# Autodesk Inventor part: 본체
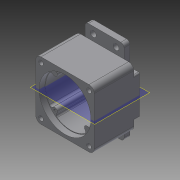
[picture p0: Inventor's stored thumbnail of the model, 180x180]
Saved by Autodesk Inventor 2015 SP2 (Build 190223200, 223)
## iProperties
Created: 2015-06
Part Number: 본체
Material: 일반
Document SubType Name: Modeling
Designer: AMC
Density: 1 g/cm^3
Appearance: 기본값
Author: AMC
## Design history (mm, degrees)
sketch "스케치1"
  geometry: L1 (-45, 45)-(45, 45); L2 (45, 45)-(45, -45); L3 (45, -45)-(-45, -45); L4 (-45, -45)-(-45, 45); 3 further points
  constraints: 8 end point, 2 midpoint, 2 parallel, 1 horizontal, 1 horizontal alignment, 1 perpendicular, 1 vertical alignment
  dimensions: "d0" = 90 distance of L2.end L3.end; "d1" = 90 distance of L1.end L2.end
extrude "돌출1" new body sketch "스케치1" distance "d2" = 61; taper "d3" = 0 deg
sketch "스케치2"
  geometry: C1 r 40 at (0, 0); 1 further point
  constraints: 1 centre point, 1 coincident
  dimensions: "d4" = 80 diameter of C1
extrude "돌출2" cut sketch "스케치2" distance "d5" = 9; taper "d6" = 0 deg
sketch "스케치3"
  geometry: C1 r 39 at (0, 0); 1 further point
  constraints: 1 centre point, 1 coincident
  dimensions: "d7" = 78 diameter of C1
extrude "돌출3" cut sketch "스케치3" distance "d8" = 61; taper "d9" = 0 deg
sketch "스케치5"
  geometry: L1 (-30, -65)-(30, -65); L2 (30, -65)-(30, 65); L3 (30, 65)-(-30, 65); L4 (-30, 65)-(-30, -65); L5 (-45, 45)-(-45, -45) reference; L6 (45, 45)-(45, -45) reference; L7 (-45, -30)-(45, -30); L8 (45, -30)-(45, 30); L9 (45, 30)-(-45, 30); L10 (-45, 30)-(-45, -30); 5 further points
  constraints: 16 end point, 4 midpoint, 4 parallel, 2 horizontal, 2 horizontal alignment, 2 perpendicular, 2 point on line, 1 vertical alignment
  dimensions: "d24" = 130 distance between parallel lines of L3 L1; "d25" = 60 distance of L1.start L1.end; "d28" = 60 distance between parallel lines of L9 L7
extrude "돌출4" join sketch "스케치5" distance "d26" = 9; taper "d27" = 0 deg
sketch "스케치7"
  geometry: C1 r 25 at (-11, 0); 1 further point
  constraints: 1 centre point
  dimensions: "d31" = 50 diameter of C1; "d32" = 11 distance of point (0, 0) C1.centre
extrude "돌출5" join sketch "스케치7" distance "d33" = 7; taper "d34" = 0 deg
sketch "스케치13"
  geometry: L1 (45, 45)-(45, -45) reference; L2 (45, -45)-(-45, -45) reference; L3 (-45, -45)-(-45, 45) reference; L4 (-45, 45)-(45, 45) reference; L5 (0, 0)-(-24.749, 24.749); L6 (0, 0)-(-33.462, 0); L7 (-21.763, 27.411)-(-24.429, 30.401); L8 (-27.411, 21.763)-(-30.401, 24.429); C1 r 40 at (0, 0) reference; C2 r 39 at (0, 0) reference; A1 r 39 centre (0, 0) between (-24.429, 30.401) and (-30.401, 24.429) reference; A2 r 4 centre (-24.749, 24.749) between (-27.411, 21.763) and (-21.763, 27.411); A3 r 35 centre (0, 0) between (-21.763, 27.411) and (-27.411, 21.763); 1 further point
  constraints: 8 end point, 6 point on circle, 2 centre point, 2 coincident, 2 tangent, 1 horizontal
  dimensions: "d56" = 35 distance of L5.start L5.end; "d57" = 45 deg angle of L6 L5; "d58" = 8 diameter of A2; "d59" = 70 diameter of A3
extrude "돌출8" join sketch "스케치13" stored distance "d60" = 20; taper "d61" = 0 deg
fillet "모깎기2" dims "d62" = 3.5
sketch "스케치17"
  geometry: A1 r 20.5 centre (11, 0) between (-8.117, -7.402) and (-8.117, 7.402); A2 r 14 centre (-20, 0) between (-8.117, 7.402) and (-8.117, -7.402); 1 further point
  constraints: 4 point on circle, 2 centre point, 2 horizontal alignment
  dimensions: "d73" = 41 diameter of A1; "d74" = 28 diameter of A2; "d75" = 11 distance of point (0, 0) A1.centre; "d76" = 20 distance of point (0, 0) A2.centre
extrude "돌출10" join sketch "스케치17" distance "d77" = 7; taper "d78" = 0 deg
sketch "스케치18"
  geometry: L1 (-40, 61)-(-40, 52) reference; L2 (-40, 52)-(-39, 52) reference; L3 (-39, 52)-(-39, 0) reference; L4 (-39, 0)-(-31.5, 0) reference; L5 (-31.5, 0)-(-31.5, 7) reference; L6 (-31.5, 7)-(34, 7) reference; L7 (34, 7)-(34, 0) reference; L8 (34, 0)-(39, 0) reference; L9 (39, 0)-(39, 52) reference; L10 (39, 52)-(40, 52) reference; L11 (40, 52)-(40, 61) reference; L12 (40, 61)-(45, 61) reference; L13 (45, 61)-(45, -9) reference; L14 (45, -9)-(14, -9) reference; L15 (14, -9)-(14, -16) reference; L16 (14, -16)-(-36, -16) reference; L17 (-36, -16)-(-36, -9) reference; L18 (-36, -9)-(-45, -9) reference; L19 (-45, -9)-(-45, 61) reference; L20 (-45, 61)-(-40, 61) reference; L21 (-36, -16)-(14, -16) reference; L22 (-11, -16)-(-11, 7); L23 (-11, -16)-(-27, -16); L24 (-27, -16)-(-27, -8); L25 (-27, -8)-(-23.5, -8); L26 (-23.5, -8)-(-23.5, -3); L27 (-28.5, 7)-(-11, 7); L28 (8.117, 7)-(-31.5, 7) reference; L29 (-23.5, -3)-(-28.5, -3); L30 (-28.5, -3)-(-28.5, 7); 1 further point
  constraints: 16 end point, 4 perpendicular, 3 point on line, 1 collinear, 1 horizontal, 1 midpoint, 1 vertical
  dimensions: "d79" = 11 distance from line of point (0, 0) L22; "d80" = 32 diameter of L24 L22; "d81" = 8 distance of L23.end L24.end; "d82" = 10 distance of L29.end L27.start; "d83" = 25 diameter of L26 L22; "d84" = 35 diameter of L30 L22
revolve "회전2" sketch "스케치18" stored, may be unused: angle "d85" = 90 deg
sketch "스케치19"
  geometry: L1 (40, 52)-(40, 61) reference; L2 (40, 61)-(45, 61) reference; L3 (45, 61)-(45, -9) reference; L4 (45, -9)-(14, -9) reference; L5 (14, -9)-(14, -16) reference; L6 (14, -16)-(5, -16) reference; L7 (5, -16)-(5, -8) reference; L8 (5, -8)-(1.5, -8) reference; L9 (1.5, -8)-(1.5, -3) reference; L10 (1.5, -3)-(6.5, -3) reference; L11 (6.5, -3)-(6.5, 7) reference; L12 (6.5, 7)-(34, 7) reference; L13 (34, 7)-(34, 0) reference; L14 (34, 0)-(39, 0) reference; L15 (39, 0)-(39, 52) reference; L16 (39, 52)-(40, 52) reference; L17 (-40, 61)-(-40, 52) reference; L18 (-40, 52)-(-39, 52) reference; L19 (-39, 52)-(-39, 0) reference; L20 (-39, 0)-(-31.5, 0) reference; L21 (-31.5, 0)-(-31.5, 7) reference; L22 (-31.5, 7)-(-28.5, 7) reference; L23 (-28.5, 7)-(-28.5, -3) reference; L24 (-28.5, -3)-(-23.5, -3) reference; L25 (-23.5, -3)-(-23.5, -8) reference; L26 (-23.5, -8)-(-27, -8) reference; L27 (-27, -8)-(-27, -16) reference; L28 (-27, -16)-(-36, -16) reference; L29 (-36, -16)-(-36, -9) reference; L30 (-36, -9)-(-45, -9) reference; L31 (-45, -9)-(-45, 61) reference; L32 (-45, 61)-(-40, 61) reference; L33 (-30, -9)-(30, -9) reference; L34 (20, 0)-(20, 7); L35 (20, 0)-(9, 0); L36 (9, 0)-(9, 7); L37 (10.5, 0)-(10.5, 0); 1 further point
  constraints: 8 end point, 4 perpendicular, 3 point on line
  dimensions: "d86" = 20 horizontal distance of point (0, 0) L34.end; "d87" = 22 diameter of L36 L34; "d88" = 7 distance of L35.end L36.end; "d89" = 19 diameter of L37 L34
revolve "회전3" sketch "스케치19" stored, may be unused: angle "d92" = 90 deg
sketch "스케치20"
  geometry: L1 (40, 52)-(40, 61) reference; L2 (40, 61)-(45, 61) reference; L3 (45, 61)-(45, -9) reference; L4 (45, -9)-(14, -9) reference; L5 (14, -9)-(14, -16) reference; L6 (14, -16)-(5, -16) reference; L7 (5, -16)-(5, -8) reference; L8 (5, -8)-(1.5, -8) reference; L9 (1.5, -8)-(1.5, -3) reference; L10 (1.5, -3)-(6.5, -3) reference; L11 (6.5, -3)-(6.5, 7) reference; L12 (6.5, 7)-(9, 7) reference; L13 (9, 7)-(9, 0) reference; L14 (9, 0)-(31, 0) reference; L15 (31, 0)-(31, 7) reference; L16 (31, 7)-(34, 7) reference; L17 (34, 7)-(34, 0) reference; L18 (34, 0)-(39, 0) reference; L19 (39, 0)-(39, 52) reference; L20 (39, 52)-(40, 52) reference; L21 (-40, 61)-(-40, 52) reference; L22 (-40, 52)-(-39, 52) reference; L23 (-39, 52)-(-39, 0) reference; L24 (-39, 0)-(-31.5, 0) reference; L25 (-31.5, 0)-(-31.5, 7) reference; L26 (-31.5, 7)-(-28.5, 7) reference; L27 (-28.5, 7)-(-28.5, -3) reference; L28 (-28.5, -3)-(-23.5, -3) reference; L29 (-23.5, -3)-(-23.5, -8) reference; L30 (-23.5, -8)-(-27, -8) reference; L31 (-27, -8)-(-27, -16) reference; L32 (-27, -16)-(-36, -16) reference; L33 (-36, -16)-(-36, -9) reference; L34 (-36, -9)-(-45, -9) reference; L35 (-45, -9)-(-45, 61) reference; L36 (-45, 61)-(-40, 61) reference; L37 (9, 0)-(31, 0) reference; L38 (20, 0)-(20, -1); L39 (20, -1)-(10.5, -1); L40 (10.5, -1)-(10.5, 0); 1 further point
  constraints: 6 end point, 1 horizontal, 1 midpoint, 1 perpendicular, 1 point on line, 1 vertical
  dimensions: "d93" = 19 diameter of L40 L38; "d94" = 1 distance between parallel lines of L14 L39
revolve "회전4" sketch "스케치20" stored, may be unused: angle "d95" = 90 deg
fillet "모깎기3" dims "d96" = 1
fillet "모깎기4" dims "d97" = 2
fillet "모깎기5" dims "d98" = 5
fillet "모깎기6" dims "d99" = 2
fillet "모깎기8" dims "d101" = 8
fillet "모깎기9" dims "d102" = 2
fillet "모깎기10" dims "d103" = 5
sketch "스케치21"
  geometry: L1 (45, 37)-(45, -37) reference; L2 (37, -45)-(-37, -45) reference; L3 (-45, -37)-(-45, 37) reference; L4 (-37, 45)-(37, 45) reference; C1 r 40 at (0, 0) reference; C2 r 3.5 at (-37, 37); A1 r 8 centre (37, 37) between (45, 37) and (37, 45) reference; A2 r 8 centre (37, -37) between (37, -45) and (45, -37) reference; A3 r 8 centre (-37, -37) between (-45, -37) and (-37, -45) reference; A4 r 8 centre (-37, 37) between (-37, 45) and (-45, 37) reference; 1 further point
  constraints: 1 centre point, 1 coincident
  dimensions: "d105" = 7 diameter of C2
extrude "돌출11" cut sketch "스케치21" stored distance "d106" = 10; taper "d107" = 0 deg
sketch "스케치22"
  geometry: L1 (45, 37)-(45, -37) reference; L2 (37, -45)-(-37, -45) reference; L3 (-45, -37)-(-45, 37) reference; L4 (-37, 45)-(37, 45) reference; L5 (-30, -45)-(-30, -60) reference; L6 (-30, -45)-(30, -45) reference; L7 (30, -60)-(30, -45) reference; L8 (-25, -65)-(25, -65) reference; L9 (30, 45)-(30, 60) reference; L10 (30, 45)-(-30, 45) reference; L11 (-30, 60)-(-30, 45) reference; L12 (25, 65)-(-25, 65) reference; L13 (-17.5, -55)-(17.5, -55); C1 r 3.5 at (37, 37) reference; C2 r 3.5 at (37, -37) reference; C3 r 3.5 at (-37, -37) reference; C4 r 3.5 at (-37, 37) reference; C5 r 40 at (0, 0) reference; C6 r 4.5 at (-17.5, -55); C7 r 4.5 at (17.5, -55); A1 r 8 centre (37, 37) between (45, 37) and (37, 45) reference; A2 r 8 centre (37, -37) between (37, -45) and (45, -37) reference; A3 r 8 centre (-37, -37) between (-45, -37) and (-37, -45) reference; A4 r 8 centre (-37, 37) between (-37, 45) and (-45, 37) reference; A5 r 5 centre (-25, -60) between (-30, -60) and (-25, -65) reference; A6 r 5 centre (25, -60) between (25, -65) and (30, -60) reference; A7 r 5 centre (25, 60) between (30, 60) and (25, 65) reference; A8 r 5 centre (-25, 60) between (-25, 65) and (-30, 60) reference; 2 further points
  constraints: 2 centre point, 2 end point, 1 horizontal, 1 horizontal alignment, 1 midpoint, 1 vertical alignment
  dimensions: "d111" = 9 diameter of C6; "d112" = 9 diameter of C7; "d113" = 35 distance of L13.end L13.start; "d114" = 55 vertical distance of point (0, 0) L13.start
extrude "돌출12" cut sketch "스케치22" stored distance "d115" = 10; taper "d116" = 0 deg
node "작업 평면2"
sketch "스케치23"
  geometry: A1 r 6 centre (-24.749, -24.749) between (-20.271, -28.742) and (-28.742, -20.271) reference; 2 further points
  constraints: 1 coincident
hole "구멍1" sketch "스케치23" at (-24.749, -24.749) diameter "d117" = 3.242; stored, may be unused: countersink angle "d121" = 90 deg, drill point angle "d123" = 118 deg; dims "d118" = 12, "d119" = 4, "d120" = 2, "d122" = 15
node "솔리드1"
pattern_circular "원형 패턴1" dims angle "d64" = 360 deg
pattern_circular "원형 패턴2" dims angle "d109" = 360 deg
mirror "대칭1"
node "투영된 루프1"
node "투영된 루프2"
node "투영된 루프3"
node "투영된 루프4"
node "절단 모서리 투영7"
node "절단 모서리 투영11"
node "절단 모서리 투영12"
node "절단 모서리 투영13"
other parameters: "d66" = 28, "d67" = 41
